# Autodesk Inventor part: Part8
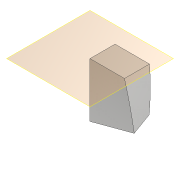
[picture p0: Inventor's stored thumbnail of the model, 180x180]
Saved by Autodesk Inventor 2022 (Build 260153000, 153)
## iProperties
Created: 2015-07
Part Number: Part8
Material: Generic
Document SubType Name: Modeling
Designer: Sandeep
Density: 1 g/cm^3
Appearance: Default
Author: Sandeep
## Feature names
1. Sweep1
## Parameters: d0 = 0, d1 = -20 deg
